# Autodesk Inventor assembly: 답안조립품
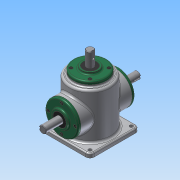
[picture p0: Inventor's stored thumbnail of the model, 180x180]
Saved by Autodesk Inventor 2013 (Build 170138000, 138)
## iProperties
Created: 2015-10
Part Number: 답안조립품
Document SubType Name: Assembly
Designer: Administrator
Author: Administrator
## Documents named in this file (14)
- C:\Users\Administrator\Desktop\451008V1007\답안조립품.iam
- C:\Users\Administrator\Desktop\451008V1007\1본체.ipt
- C:\Users\Administrator\Desktop\451008V1007\커버.ipt
- C:\Users\Administrator\Desktop\451008V1007\베어링 6203.ipt
- C:\Users\Administrator\Desktop\451008V1007\M4.ipt
- C:\Users\Administrator\Desktop\451008V1007\오일실.ipt
- C:\Users\Administrator\Desktop\451008V1007\메인 축.ipt
- 메인 축.ipt
- C:\Users\Administrator\Desktop\451008V1007\키 5x5.ipt
- C:\Users\Administrator\Desktop\451008V1007\서브 축.ipt
- 서브 축.ipt
- C:\Users\Administrator\Desktop\451008V1007\키 4x4.ipt
- C:\Users\Administrator\Desktop\451008V1007\메인 베벨기어.ipt
- C:\Users\Administrator\Desktop\451008V1007\서브 베벨기어.ipt
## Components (13 placed, 2 different names)
1. 1본체:1 — 각도:3, 각도:4
2. M4:1
3. M4:3
4. M4:4
5. M4:5
6. M4:2
7. M4:6
8. M4:7
9. M4:8
10. M4:9
11. M4:10
12. M4:11
13. M4:12
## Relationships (2: Angle 2)
- 각도:3 [Angle]: 1본체:1
- 각도:4 [Angle]: 1본체:1
